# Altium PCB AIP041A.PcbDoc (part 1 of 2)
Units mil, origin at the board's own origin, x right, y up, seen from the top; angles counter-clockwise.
Board outline 2650 x 1600 mil, 2 copper layers (Top Layer, Bottom Layer), stack 62 mil thick; 99 components, 51 nets, 275 pads, 83 vias.
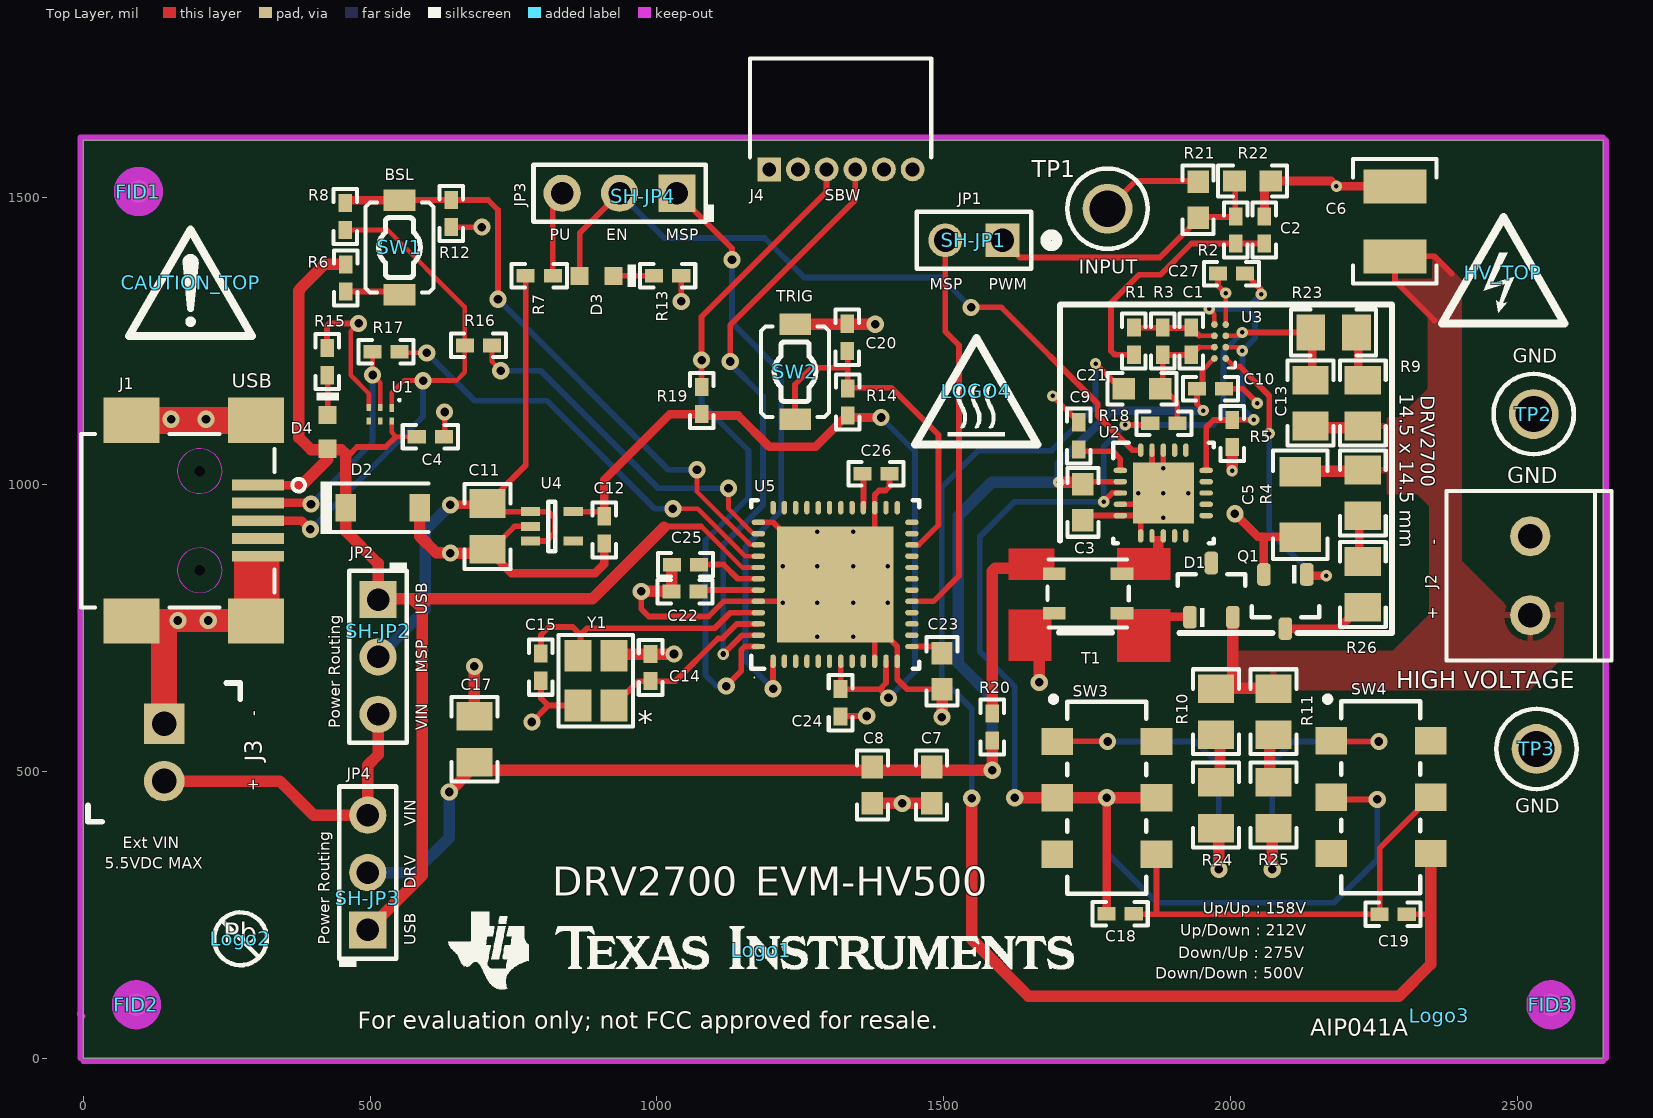
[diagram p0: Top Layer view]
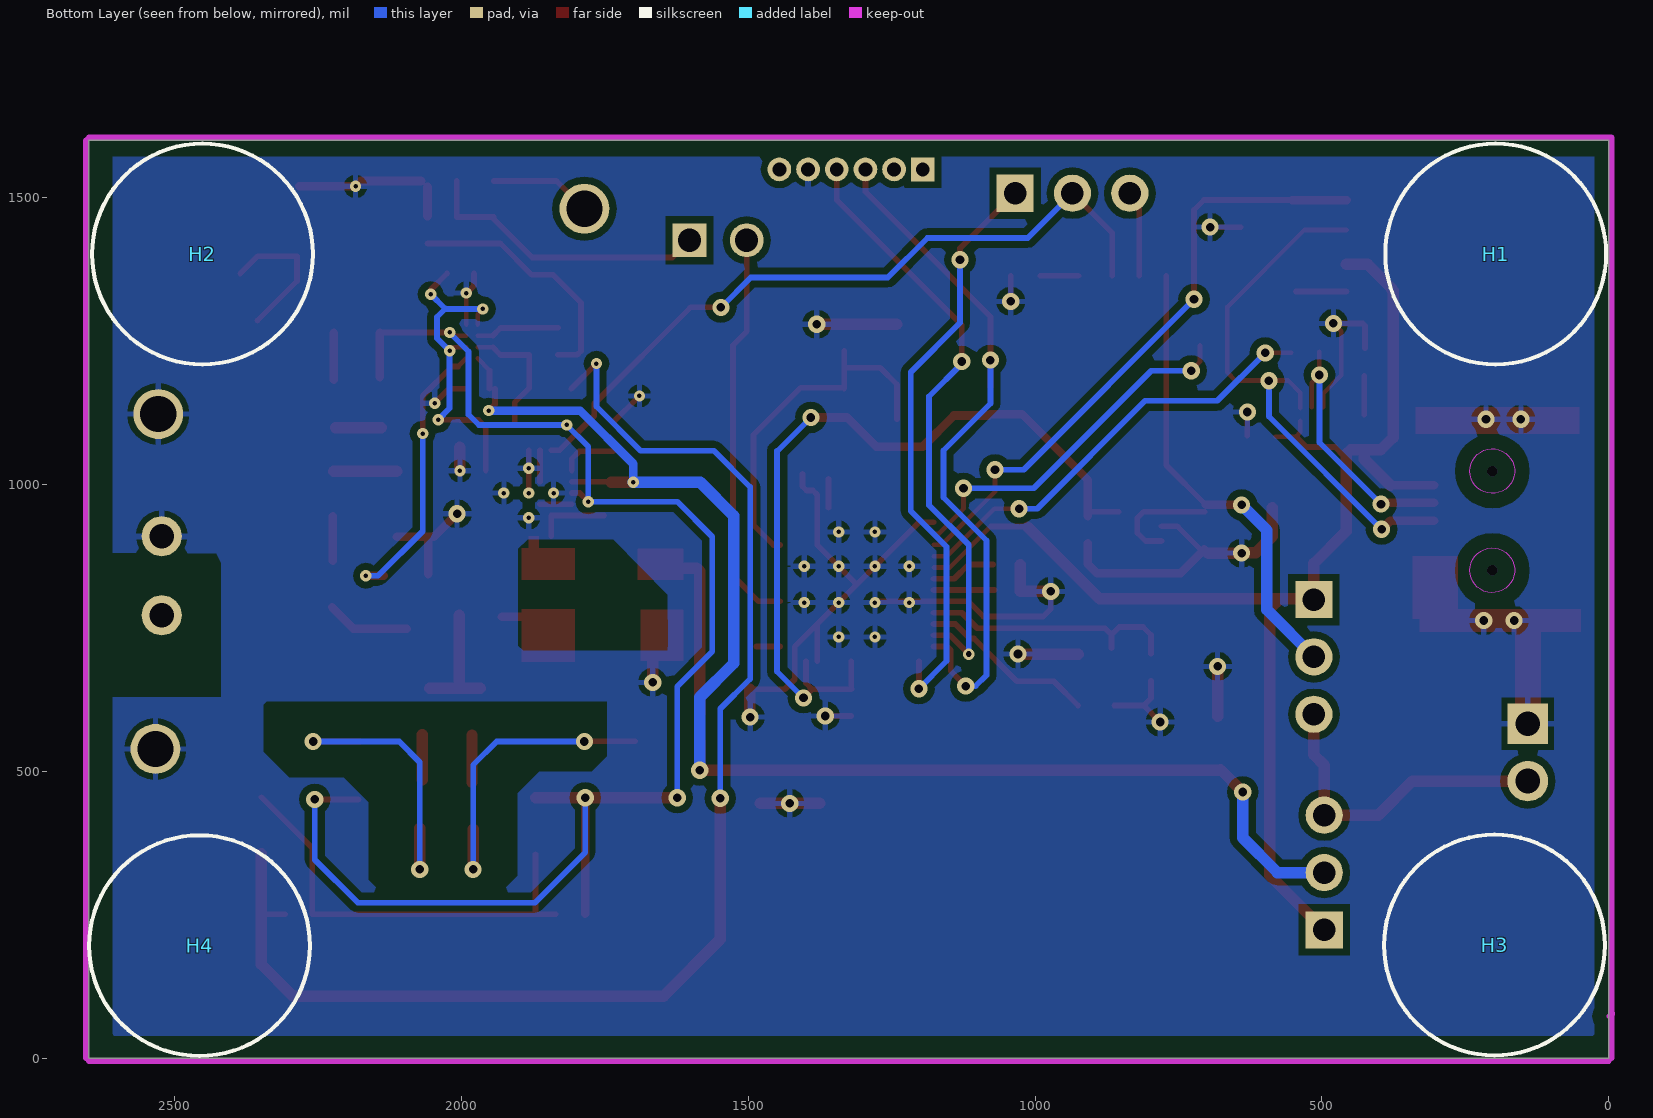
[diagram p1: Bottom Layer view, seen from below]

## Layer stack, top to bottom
Top Layer: signal copper 1.4
Dielectric: core 59.2, FR-4, Dk 4.8
Bottom Layer: signal copper 1.4

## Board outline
0,0 0,1600 2650,1600 2650,0 0,0

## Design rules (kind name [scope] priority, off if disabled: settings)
AcuteAngle [All] p1: minimum=4.50000000000000E+0001 checktracksonly=FALSE
AssemblyTestPointUsage [All] p1: valid=2
Clearance Clearance_BoardEdge_MountingHoles [OnCopper and InComponentClass('Mounting Holes') vs IsKeepOut] p1: gap=30
Clearance Clearance_BoardEdge_Poly [OnCopper and InPoly vs IsKeepOut] p2: gap=25
Clearance Clearance_BoardEdge [OnCopper and Not InComponentClass('Logo') and not InComponentClass('FiducialMark') and not InRegion(1000,500,4000,800) and Not IsKeepout vs IsKeepOut] p3: gap=18
Clearance Clearance_Poly [InPolygon] p4: gap=12
Clearance [All vs InNetClass('HV')] p5: gap=30
ComponentClearance ComponentClearance_Shunt [InComponentClass('Header') vs InComponentClass('Shunt')] p1: gap=0 collisioncheckmode=3 verticalgap=0 showdistances=FALSE
ComponentClearance ComponentClearance_Logo [InComponentClass('Logo')] p2: gap=30 collisioncheckmode=3 verticalgap=10 showdistances=FALSE
ComponentClearance ComponentClearance_ScrewToNut [(HasFootprint('NY PMS 440 0025 PH')) vs (HasFootprint('Keystone_1902C'))] p3: gap=5 collisioncheckmode=3 verticalgap=10 showdistances=FALSE
ComponentClearance ComponentClearance_MountingHoles [InComponentClass('Mounting Holes')] p4: gap=50 collisioncheckmode=3 verticalgap=100 showdistances=FALSE
ComponentClearance ComponentClearance_SmallPassives [HasFootprint('0201*') or HasFootprint('0402*') or HasFootprint('0508') or HasFootprint('0603*') or HasFootprint('0612') or HasFootprint('0805*') or HasFootprint('0815*') or HasFootprint('0830*') or HasFootprint('1206*') or HasFootprint('1210*') or HasFootprint('1808*') or HasFootprint('1812*') or HasFootprint('1825*') or HasFootprint('2010*') or HasFootprint('2220*') or HasFootprint('2225*') or HasFootprint('2512*') or HasFootprint('2728*') or HasFootprint('3518*') vs HasFootprint('0201*') or HasFootprint('0402*') or HasFootprint('0508') or HasFootprint('0603*') or HasFootprint('0612') or HasFootprint('0805*') or HasFootprint('0815*') or HasFootprint('0830*') or HasFootprint('1206*') or HasFootprint('1210*') or HasFootprint('1808*') or HasFootprint('1812*') or HasFootprint('1825*') or HasFootprint('2010*') or HasFootprint('2220*') or HasFootprint('2225*') or HasFootprint('2512*') or HasFootprint('2728*') or HasFootprint('3518*')] p5: gap=12 collisioncheckmode=3 verticalgap=10 showdistances=FALSE
ComponentClearance ComponentClearance_THtoSMT [IsThruComponent vs IsSMTComponent] p6: gap=75 collisioncheckmode=3 verticalgap=30 showdistances=FALSE
ComponentClearance ComponentClearance_THtoTH [IsThruComponent vs IsThruComponent] p7: gap=70 collisioncheckmode=3 verticalgap=30 showdistances=FALSE
ComponentClearance [All] p8: gap=12 collisioncheckmode=3 verticalgap=10 showdistances=FALSE
DiffPairsRouting [All] p1: maxlimit=100 minlimit=10 mostfreqgap=10 maxuncoupledlength=1000
FabricationTestPointUsage TestPointUsage [All] p1: valid=2 allowmultiple=FALSE
FabricationTestpoint Testpoint [All] p1: side=3 testpointundercomponent=TRUE minsize=40 maxsize=100 preferedsize=60 minholesize=0 maxholesize=40 preferedholesize=32 testpointgrid=1 allowsidetop=TRUE allowsidebottom=TRUE usegrid=TRUE gridtolerance=0.01
FanoutControl Fanout_LCC [IsLCC] p1: bgadir=Out bgaviamode=Centered fanoutstyle=Auto fanoutdirection=Alternating viagrid=1 // Fanout_LCC (Default Rule)
FanoutControl Fanout_BGA [IsBGA] p2: bgadir=Out bgaviamode=Centered fanoutstyle=Auto fanoutdirection=Alternating viagrid=1 // Fanout_BGA (Default Rule)
FanoutControl Fanout_Default [All] p4: bgadir=Out bgaviamode=Centered fanoutstyle=Auto fanoutdirection=Alternating viagrid=1 // Fanout_Default (Default Rule)
FanoutControl Fanout_Small [(CompPinCount < 5)] p5: bgadir=Out bgaviamode=Centered fanoutstyle=Auto fanoutdirection=OutThenIn viagrid=1 // Fanout_Small (Default Rule)
HoleSize [All] p1: absolutevalues=TRUE maxlimit=251 minlimit=3 maxpercent=80.000 minpercent=20.000
MinimumAnnularRing MinimumAnnularRing_ThermalPadVias [IsVia and InAnyComponent] p1: minimumring=5.91
MinimumAnnularRing [All] p2: minimumring=2
MinimumSolderMaskSliver MinimumSolderMaskSliver_Logo [InComponentClass('Logo') vs InComponentClass('Logo')] p1: minsoldermaskwidth=0.7
MinimumSolderMaskSliver [All] p2: minsoldermaskwidth=4
PlaneClearance [All] p1: clearance=12
PlaneConnect [All] p1: planeconnectstyle=Relief reliefexpansion=10 reliefentries=4 reliefconductorwidth=10 reliefairgap=10
PolygonConnect [All] p1: connectstyle=Relief reliefconductorwidth=10 reliefentries=4 polygonreliefangle="90 Angle" airgapwidth=10
RoutingVias ThermalPadVias [IsVia and InAnyComponent] p1: holewidth=7.87 width=19.68 viastyle="Through Hole" minholewidth=7.87 minwidth=19.68 maxholewidth=12.99 maxwidth=23.62
RoutingVias [All] p2: holewidth=16 width=34 viastyle="Through Hole" minholewidth=5 minwidth=10 maxholewidth=40 maxwidth=65
SMDToCorner [All] p1 off: distance=30000
SilkToSilkClearance SilkToSilkClearance_Pb-Free [(HasFootprint('Pb-Free_Overlay_Medium') OR HasFootprint('Pb-Free_Overlay_Small')) vs (HasFootprint('Pb-Free_Overlay_Medium') OR HasFootprint('Pb-Free_Overlay_Small'))] p1: silktosilkclearance=0
SilkToSilkClearance [All] p2: silktosilkclearance=2
SilkscreenOverComponentPads [IsPad] p1: minsilkscreentomaskgap=1
SolderMaskExpansion [All] p1: expansion=1
Width [All] p1: maxlimit=100 minlimit=3 preferedwidth=10 checkconnectedcopper=TRUE
13 further rules are at their usual default settings.

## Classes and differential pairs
net class HV: HV NetQ1_3 RNET1 RNET2
component class AssemblyNote: ZZ2 ZZ3 ZZ4
component class FiducialMark: FID1 FID2 FID3
component class AIP041A_Hardware: CAUTION_TOP FID1 FID2 FID3 H1 H2 H3 H4 HV_TOP Logo1 Logo2 Logo3 LOGO4 SH-JP1 SH-JP2 SH-JP3 SH-JP4 ZZ2 ZZ3 ZZ4
component class Logo: Logo1
component class Header: JP1 JP2 JP3 JP4
component class AIP041A: C1 C2 C3 C4 C5 C6 C7 C8 C9 C10 C11 C12 C13 C14 C15 C17 C18 C19 C20 C21 C22 C23 C24 C25 C26 C27 D1 D2 D3 D4 J1 J2 J3 J4 JP1 JP2 JP3 JP4 Q1 R1 R2 R3 R4 R5 R6 R7 R8 R9 R10 R11 R12 R13 R14 R15 R16 R17 R18 R19 R20 R21 R22 R23 R24 R25 R26 SW1 SW2 SW3 SW4 T1 TP1 TP2 TP3 U1 U2 U3 U4 U5 Y1
component class Shunt: SH-JP1 SH-JP2 SH-JP3 SH-JP4

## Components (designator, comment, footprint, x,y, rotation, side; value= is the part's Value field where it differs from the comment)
C1 "GRM1555C1H101JA01D" 0402 1932.12,1250 r90 top
C2 "GRM155R61A102KA01D" 0402 2059.49,1444.01 r90 top
C3 "GRM188R71E104KA01D" 0603 1743,969 r270 top
C4 "GRM155R71C104JA88D" 0402 605,1083.52 r0 top
C5 "GRM31B5C2J102JW01L" 1206 2122,965 r270 top
C6 "GRM32DR72J473KW01L" 1210M 2287,1459 r90 top
C7 "GRM188R71E104KA01D" 0603 1479,476 r270 top
C8 "GRM188R61E106MA73" 0603 1376,476 r270 top
C9 "GRM155R71C104JA88D" 0402 1736,1085 r90 top
C10 "GRM155R71C104JA88D" 0402 1965.38,1167 r0 top
C11 "0805YD106MAT2A" 0805_HV 705,927.15 r270 top
C12 "GRM155R60J102KA01D" 0402 908,921.15 r270 top
C13 "C0805C220KBRACTU" 0805_HV 2140,1142 r90 top
C14 "GRM1555C1H100JA01D" 0402 989,680.9 r270 top
C15 "GRM1555C1H100JA01D" 0402 798,681.52 r90 top
C17 "0805YD106MAT2A" 0805_HV 682,556 r90 top
C18 "GRM155R71E562KA01D" 0402 1808,252 r0 top
C19 "GRM155R71H332KA01D" 0402 2284,251 r0 top
C20 "C1005X5R0J104K" 0402 1332.05,1256.84 r90 top
C21 "GRM188R72A472KA01D" 0603 1846,1167 r0 top
C22 "GRM155C80J224KE01D" 0402 1049.38,813.52 r180 top
C23 "C0603C474K8RACTU" 0603 1497.29,674.57 r270 top
C24 "C1005X5R0J104K" 0402 1320.29,619.57 r90 top
C25 "GRM155C80J224KE01D" 0402 1050,860.52 r180 top
C26 "C1005X5R0J104K" 0402 1382,1018.52 r180 top
C27 "GRM155R71C104JA88D" 0402 2002,1368 r180 top
CAUTION_TOP "CAUTION.  READ USER GUIDE BEFORE USE" IEC_Caution_Small 187,1352 r0 top
D1 "MMBD3004S-7-F" SOT-23 1967,816 r90 top
D2 "MMSZ5232B-7-F" SOD-123 522,959.52 r0 top
D3 "LTST-C190KGKT" LED_LTST-C190_G 895,1364 r0 top
D4 "LTST-C190KGKT" LED_LTST-C190_G 426,1092.03 r90 top
FID1 "Fiducial" Fiducial10-20 96,1511 r0 top
FID2 "Fiducial" Fiducial10-20 92.5,93 r0 top
FID3 "Fiducial" Fiducial10-20 2559,93 r0 top
H1 "SJ61A2" Bumpon_SJ61A2 197,1402 r270 bottom
H2 "SJ61A2" Bumpon_SJ61A2 2452,1402 r270 bottom
H3 "SJ61A2" Bumpon_SJ61A2 199,197 r270 bottom
H4 "SJ61A2" Bumpon_SJ61A2 2457,196 r270 bottom
HV_TOP "DANGER HIGH VOLTAGE" IEC_HighVoltage_Small 2476,1369 r0 top
J1 "USB" MILLMAX_897-43-005-00-100001 152,937 r270 top
J2 "1751248" CONN_1751248 2523,841 r90 top
J3 "1725656" CONN_1725656 141,533 r270 top
J4 "LPPB061NGCN-RC" SULLINS_LPPB061NGCN-RC 1321,1649.52 r180 top
JP1 "5-146261-1" CONN_5-146261-1 1553,1426 r180 top
JP2 "5-146278-3" TE_5-146278-3 514,699.52 r270 top
JP3 "5-146278-3" TE_5-146278-3 935,1508 r180 top
JP4 "5-146278-3" TE_5-146278-3 496,323.52 r90 top
Logo1 "Texas Instruments" TI_Horizontal_Overlay_Small 1182,188 r0 top
Logo2 "Pb-Free Symbol" Pb-Free_Overlay_Small 274,208 r0 top
Logo3 "FCC disclaimer" FCC_disclaimer 2364,74 r0 top
LOGO4 "CAUTION HOT SURFACE" IEC_HotSurface_Small 1557,1163 r0 top
Q1 "BSS127 H6327" SOT-23 2096,796 r270 top
R1 "CRCW0402100KFKED" 0402 1832,1250 r90 top
R2 "CRCW04024K99FKED" 0402 2009.49,1444.01 r270 top
R3 "CRCW040275K0JNED" 0402 1882.12,1250 r90 top
R4 "CRCW08052K40JNEA" 0805_HV 2231,985.49 r90 top
R5 "CRCW040210K0JNED" 0402 2003,1089 r270 top
R6 "CRCW0402100RFKED" 0402 457.37,1360.38 r90 top
R7 "CRCW04023K30JNED" 0402 795,1364 r180 top
R8 "CRCW04021K40FKED" 0402 457,1467.52 r270 top
R9 "CRCW08051M00FKEA" 0805_HV 2231,1142 r270 top
R10 "RT0805BRD07750KL" 0805_HV 1975,604 r90 top
R11 "CRCW08051M24FKEA" 0805_HV 2075,604 r90 top
R12 "CRCW04021M00JNED" 0402 641.52,1472.51 r90 top
R13 "CRCW0402511RFKED" 0402 1019,1364 r180 top
R14 "CRCW040210K0JNED" 0402 1333.05,1143.84 r270 top
R15 "CRCW0402511RFKED" 0402 425,1214.24 r270 top
R16 "CRCW040233R0JNED" 0402 689,1242.52 r180 top
R17 "CRCW040233R0JNED" 0402 528,1231.52 r180 top
R18 "CRCW04025K49FKED" 0402 1884,1107 r180 top
R19 "CRCW04029K76FKED" 0402 1078,1146.52 r270 top
R20 "RC0402JR-070RL" 0402 1585,577 r270 top
R21 "CRCW06030000Z0EA" 0603 1943.8,1496.51 r90 top
R22 "CRCW06030000Z0EA" 0603 2038.8,1529.29 r180 top
R23 "CRCW08051M05FKEA" 0805_HV 2180,1265 r0 top
R24 "RT0805BRD07750KL" 0805_HV 1975,441 r90 top
R25 "CRCW08051M24FKEA" 0805_HV 2075,441 r90 top
R26 "CRCW08052K40JNEA" 0805_HV 2231,826 r90 top
SH-JP1 "2SN-BK-G" 2SN-BK-G 1553,1426 r180 top
SH-JP2 "2SN-BK-G" 2SN-BK-G 514,744.39 r90 top
SH-JP3 "2SN-BK-G" 2SN-BK-G 496,278.66 r90 top
SH-JP4 "2SN-BK-G" 2SN-BK-G 976.68,1503.01 r180 top
SW1 "BSL" SW_TL1015AF160QG 551.37,1413.38 r270 top
SW2 "TRIG" SW_TL1015AF160QG 1241.05,1196.84 r270 top
SW3 "CL-SB-22B-02T" SW_CL-SB-22B-02 1784.59,453.88 r0 top
SW4 "CL-SB-22B-02T" SW_CL-SB-22B-02 2262.59,454.88 r0 top
T1 "ATB322515-0110" XFMR_ATB3215 1752,810 r270 top
TP1 "INPUT" Keystone5013 1786,1481 r0 top
TP2 "GND" Keystone5011 2529,1123 r90 top
TP3 "GND" Keystone5011 2534,539 r0 top
U1 "TPD4E004DRY" DRY0006A 517.8,1122.73 r270 top
U2 "DRV2700RGP" RGP0020D 1883.08,985.27 r0 top
U3 "OPA2376AIYZD" YZD0008ANAP 1982.12,1249.5 r180 top
U4 "TLV70033DCKR" DCK0005A_N 817,927.15 r0 top
U5 "MSP430F5510IRGZ" RGZ0048A 1310.99,825.88 r90 top
Y1 "ABM8G-12.000MHZ-B4Y-T" XTAL_NX3225SA 893.82,658.01 r90 top
ZZ2 "These assemblies are ESD sensitive, ESD precautions shall be observed." AssemblyNote 185,3829.11 r0 top
ZZ3 "These assemblies must be clean and free from flux and all contaminants. Use of no clean flux is not acceptable." AssemblyNote 185,3740.56 r0 top
ZZ4 "These assemblies must comply with workmanship standards IPC-A-610 Class 2, unless otherwise specified." AssemblyNote 185,3652 r0 top

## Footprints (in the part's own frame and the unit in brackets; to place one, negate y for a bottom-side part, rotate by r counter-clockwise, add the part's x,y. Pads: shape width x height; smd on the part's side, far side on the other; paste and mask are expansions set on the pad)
2SN-BK-G [mil] "Samtec STEP model"
  round 1 on Mech3: 0(0,0)
  body extent -78,-39 79,39, height 188
0402 [mm] "0402 from SM-752 data"
  rect 0.8x0.6 smd: 1(-0.6,0) 2(0.6,0)
  silkscreen extent -1.22,-0.52 1.22,0.52, body extent -0.55,-0.3 0.55,0.3, height 0.6
0603 [mm] "0603 from SM-752 data"
  rect 1x0.95 smd: 1(-0.8,0) 2(0.8,0)
  silkscreen extent -1.52,-0.69 1.52,0.69, body extent -0.87,-0.47 0.87,0.47, height 0.85
0805_HV [mil] "0805 with 30mil clearance between pads"
  rect 50x63 smd: 1(-40,0) 2(40,0)
  silkscreen extent -74,-40 74,40, body extent -43,-29 43,29, height 43
1206 [mm] "1206 from SM-752 data"
  rect 1.3x1.85 smd: 1(-1.45,0) 2(1.45,0)
  silkscreen extent -2.4,-1.21 2.4,1.21, body extent -1.7,-0.9 1.7,0.9, height 1.35
1210M [mm] "1210 from SM-752 data"
  rect 1.5x2.8 smd: 1(-1.55,0) 2(1.55,0)
  silkscreen extent -2.75,-1.85 2.75,1.85, body extent -1.7,-1.35 1.7,1.35, height 1.35
AssemblyNote [mil] "Assembly Note"
Bumpon_SJ61A2 [mil] "3M Hemispherical Bumpon transparent"
  round 1 on Mech4: 0(0,0)
  silkscreen extent -192,-192 192,192, body extent -191,-192 193,192, height 250
CONN_5-146261-1 [mm] "Sullins"
  rect 1.5x1.5 hole 1.02: 1(-1.27,0)
  round 1.5 hole 1.02: 2(1.27,0)
  silkscreen extent -3.68,-1.27 2.54,1.27, body extent -2.51,-1.27 2.51,1.27, height 10.87
CONN_1725656 [mm] "Phoenix Contact"
  rect 1.8x1.8 hole 1.1: 1(-1.27,0)
  round 1.8 hole 1.1: 2(1.27,0)
  silkscreen extent -3.08,-3.37 3.08,3.37, body extent -2.77,-3.1 2.77,3.1, height 8.52
CONN_1751248 [mil] "Phoenix Contact"
  round 70 hole 43.31: 1(-68.9,0) 2(68.9,0)
  silkscreen extent -148,-142 148,146, body extent -148,-142 148,146, height 335
DCK0005A_N [mm] "SOT353, 5-Leads, Body 2x1.3mm, Pitch 0.65mm, Lead Span 2.1mm, IPC Medium Density"
  rect 0.85x0.4 smd: 1(-0.95,0.65) 2(-0.95,0) 3(-0.95,-0.65) 4(0.95,-0.65) 5(0.95,0.65)
  silkscreen extent -0.15,-1.1 0.15,1.1, body extent -1.14,-1 1.14,1, height 0.94
DRY0006A [mm] "PSON, 6-Leads, Body 1x1.45mm, Pitch 0.5mm, TI Recommended"
  rect 0.35x0.2 smd: 1(-0.275,0.5)
  rect 0.3x0.2 smd: 2(-0.3,0) 3(-0.3,-0.5) 4(0.3,-0.5) 5(0.3,0) 6(0.3,0.5)
  silkscreen extent -0.67,0.8 -0.58,0.9, body extent -0.53,-0.75 0.53,0.75, height 0.61
FCC_disclaimer [mil]
Fiducial10-20 [mm]
  round 1 smd mask+0.5: 1(0,0)
  Top Layer keep-out circle w1.178: c0,0 r0.5
IEC_Caution_Small [mil]
  silkscreen extent -107,-93 107,92
IEC_HighVoltage_Small [mil]
  silkscreen extent -107,-88 107,97
IEC_HotSurface_Small [mil]
  silkscreen extent -107,-93 107,92
Keystone5011 [mil] "Keystone Multipurpose loops"
  round 87 hole 63: 1(0,0)
  silkscreen extent -70,-70 70,70, body extent -63,-63 63,62, height 319
Keystone5013 [mil] "Keystone Multipurpose loops"
  round 87 hole 63: 1(0,0)
  silkscreen extent -70,-70 70,70, body extent -63,-63 63,62, height 319
LED_LTST-C190_G [mm] "Lite-On"
  rect 0.8x0.8 smd: 1(-0.75,0) 2(0.75,0)
  silkscreen extent 1.37,-0.5 1.75,0.5, body extent -0.85,-0.45 0.85,0.45, height 0.9
MILLMAX_897-43-005-00-100001 [mil] "Mill-Max"
  rect 19x91 smd: 1(-62,152.5) 2(-31,152.5) 3(0,152.5) 4(31,152.5) 5(62,152.5)
  rect 79x98 smd: 6(175,149) 7(-175,149) 8(-175,-68) 9(175,-68)
  round 5 hole 18 unplated: MH1(-86.5,51) MH2(86.5,51)
  Multi-Layer keep-out circle w1: c-86.5,51 r39
  Multi-Layer keep-out circle w1: c86.5,51 r39
  silkscreen extent -152,-156 152,234, body extent -151,-181 151,181, height 156
Pb-Free_Overlay_Small [mil]
  silkscreen extent -46,-46 46,46
RGP0020D [mm] "QFN, 20-Leads, Body 4x4mm, Pitch 0.5mm, Thermal Pad 2.7x2.7mm, TI Recommended"
  oval 0.6x0.24 smd: 1(-1.9,1) 2(-1.9,0.5) 3(-1.9,0) 4(-1.9,-0.5) 5(-1.9,-1) 11(1.9,-1) 12(1.9,-0.5) 13(1.9,0) 14(1.9,0.5) 15(1.9,1)
  oval 0.24x0.6 smd: 6(-1,-1.9) 7(-0.5,-1.9) 8(0,-1.9) 9(0.5,-1.9) 10(1,-1.9) 16(1,1.9) 17(0.5,1.9) 18(0,1.9) 19(-0.5,1.9) 20(-1,1.9)
  rect 2.7x2.7 smd paste-1.35: 21(0,0)
  silkscreen extent -2.22,-2.22 2.22,2.22, body extent -2.07,-2.07 2.07,2.07, height 1.01
RGZ0048A [mm] "QFN, 48-Leads, Body 7x7mm, Pitch 0.5mm, Thermal Pad 5.15X5.15mm, TI recommended"
  oval 0.6x0.24 smd: 1(-3.4,2.75) 2(-3.4,2.25) 3(-3.4,1.75) 4(-3.4,1.25) 5(-3.4,0.75) 6(-3.4,0.25) 7(-3.4,-0.25) 8(-3.4,-0.75) 9(-3.4,-1.25) 10(-3.4,-1.75) 11(-3.4,-2.25) 12(-3.4,-2.75) 25(3.4,-2.75) 26(3.4,-2.25) 27(3.4,-1.75) 28(3.4,-1.25) 29(3.4,-0.75) 30(3.4,-0.25) 31(3.4,0.25) 32(3.4,0.75) 33(3.4,1.25) 34(3.4,1.75) 35(3.4,2.25) 36(3.4,2.75)
  oval 0.24x0.6 smd: 13(-2.75,-3.4) 14(-2.25,-3.4) 15(-1.75,-3.4) 16(-1.25,-3.4) 17(-0.75,-3.4) 18(-0.25,-3.4) 19(0.25,-3.4) 20(0.75,-3.4) 21(1.25,-3.4) 22(1.75,-3.4) 23(2.25,-3.4) 24(2.75,-3.4) 37(2.75,3.4) 38(2.25,3.4) 39(1.75,3.4) 40(1.25,3.4) 41(0.75,3.4) 42(0.25,3.4) 43(-0.25,3.4) 44(-0.75,3.4) 45(-1.25,3.4) 46(-1.75,3.4) 47(-2.25,3.4) 48(-2.75,3.4)
  rect 5.15x5.15 smd paste-2.6: 49(0,0)
  silkscreen extent -3.72,-3.72 3.72,3.72, body extent -3.58,-3.57 3.57,3.58, height 1.01
SOD-123 [mm] "On Semi recommended land pattern"
  rect 0.915x1.22 smd: 1(-1.637,0) 2(1.637,0)
  silkscreen extent -2.74,-1.17 2.03,1.17, body extent -1.93,-0.9 1.93,0.9, height 1.35
SOT-23 [mm] "SOT23, 3-Leads, Body 2.9x1.3mm, Pitch 0.95mm, Lead Span 2.5mm, IPC Medium Density"
  rrect50% 1x0.6 smd: 1(-1.2,0.95) 2(-1.2,-0.95) 3(1.2,0)
  silkscreen extent -1.63,-1.5 0.7,1.5, body extent -1.16,-1.45 1.21,1.45, height 1
SULLINS_LPPB061NGCN-RC [mm] "SULLINS"
  rect 1.05x1.05 hole 0.61: 1(3.175,2.54)
  round 1.05 hole 0.61: 2(1.905,2.54) 3(0.635,2.54) 4(-0.635,2.54) 5(-1.905,2.54) 6(-3.175,2.54)
  silkscreen extent -4,-2.37 4.03,2, body extent -4,-2.36 4,2.59, height 2.16
SW_CL-SB-22B-02 [mm] "SMD, 6-Leads, Body 8.5x3.5mm, Pitch 2.5mm"
  rect 1.4x1.2 smd: 1(-2.2,2.5) 2(-2.2,0) 3(-2.2,-2.5) 4(2.2,2.5) 5(2.2,0) 6(2.2,-2.5)
  silkscreen extent -2.48,-4.25 1.75,4.49, body extent -1.75,-4.25 1.75,4.25, height 5.5
SW_TL1015AF160QG [mm] "E-Switch"
  rect 0.95x1.4 smd: 1(-2.1,0) 2(2.1,0)
  silkscreen extent -2,-1.5 2,1.5, body extent -2.3,-1.5 2.3,1.5, height 2
TE_5-146278-3 [mm] "TE CONNECTIVITY"
  rect 1.65x1.65 hole 1: 1(-2.54,0)
  round 1.65 hole 1: 2(0,0) 3(2.54,0)
  silkscreen extent -4.19,-1.27 3.81,1.27, body extent -3.68,-1.17 3.68,1.17, height 8.13
TI_Horizontal_Overlay_Small [mil]
  silkscreen extent -545,-68 545,67
XFMR_ATB3215 [mm] "TDK"
  rect 0.55x1 smd: 1(-0.875,1.5) 2(0.875,1.5) 3(0.875,-1.5) 4(-0.875,-1.5)
  silkscreen extent -1.5,-1.8 1.5,1.8, body extent -1.4,-1.75 1.4,1.75, height 1.55
XTAL_NX3225SA [mm] "NDK NX3225SA recommended land pattern"
  rect 1.4x1.2 smd: 1(-1.1,-0.8) 2(1.1,-0.8) 3(1.1,0.8) 4(-1.1,0.8)
  silkscreen extent -2.03,-1.65 2.03,1.65, body extent -1.65,-1.3 1.65,1.3, height 0.7
YZD0008ANAP [mm] "WCSP"
  round 0.3 smd paste-0.1 mask+0.04: A1(-0.25,0.75) A2(0.25,0.75) B1(-0.25,0.25) B2(0.25,0.25) C1(-0.25,-0.25) C2(0.25,-0.25) D1(-0.25,-0.75) D2(0.25,-0.75)
  silkscreen extent -0.67,0.92 -0.35,1.17, body extent -0.57,-1.09 0.57,1.09, height 0.63

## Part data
C1: "CAP, CERM, 100 pF, 50 V, +/- 5%, C0G/NP0, 0402"
C2: "CAP, CERM, 1000 pF, 10 V, +/- 10%, X5R, 0402"
C3 C7: "CAP, CERM, 0.1 µF, 25 V, +/- 10%, X7R, 0603"
C4 C9 C10 C27: library part 0402YC132KAT2A, "CAP CER 0.1UF 16V 5% X7R 0402"
C5: "CAP, CERM, 1000 pF, 630 V, +/- 5%, C0G/NP0, 1206"
C6: "CAP, CERM, 0.047 µF, 630 V, +/- 10%, X7R, 1210"
C8: "CAP, CERM, 10 µF, 25 V, +/- 20%, X5R, 0603"
C11 C17: "CAP, CERM, 10uF, 16V, +/-20%, X5R, 0805"
C12: "CAP, CERM, 1000pF, 6.3V, +/-10%, X5R, 0402"
C13: "CAP, CERM, 22 pF, 630 V, +/- 10%, X7R, 0805_140"
C14 C15: "CAP, CERM, 10pF, 50V, +/-5%, C0G/NP0, 0402"
C18: "CAP, CERM, 5600 pF, 25 V, +/- 10%, X7R, 0402"
C19: "CAP, CERM, 3300 pF, 50 V, +/- 10%, X7R, 0402"
C20 C24 C26: "CAP, CERM, 0.1uF, 6.3V, +/-10%, X5R, 0402"
C21: "CAP, CERM, 4700 pF, 100 V, +/- 10%, X7R, 0603"
C22 C25: "CAP, CERM, 0.22uF, 6.3V, +/-10%, X6S, 0402"
C23: "CAP, CERM, 0.47uF, 10V, +/-10%, X7R, 0603"
CAUTION_TOP: library part IEC_Caution, "IEC 61010-1 Caution Warning"
D1: "Diode, Switching, 350 V, 0.225 A, SOT-23"
D2: "Diode, Zener, 5.6V, 500 mW, SOD-123"
D3 D4: "LED, Green, SMD"
FID1 FID2 FID3: "Fiducial mark.  There is nothing to buy or mount."
H1 H2 H3 H4: "Bumpon, Hemisphere, 0.375 X 0.235, Black"
HV_TOP: library part IEC_HighVoltage, "IEC 61010-1 High Voltage Warning"
J1: library part 897-43-005-00-100001, "Connector, USB Mini B"
J2: "Conn Term Block, 2POS, 3.5mm, TH"
J3: "Header, 2 Pos, 6A, 63V, TH"
J4: "Receptacle, 50mil, 6x1, R/A, TH"
JP1: "Header, 100mil, 2x1, Gold, TH"
JP2 JP3 JP4: "Header, 100mil, 3x1, Tin, TH"
Logo1: library part TI_Logo, "Texas Instrument Corporate Signature"
Logo2: library part Pb-Free
Logo3: library part FCC_disclaimer, "FCC_disclaimer"
LOGO4: library part IEC_HotSurface, "IEC 61010-1 Hot Surface Warning"
Q1: "MOSFET, N-CH, 600 V, 0.021 A, SOT-23"
R1: "RES, 100 k, 1%, 0.063 W, 0402"
R2: "RES, 4.99 k, 1%, 0.063 W, 0402"
R3: "RES, 75 k, 5%, 0.063 W, 0402"
R4 R26: "RES, 2.4 k, 5%, 0.125 W, 0805"
R5: "RES, 10 k, 5%, 0.063 W, 0402"
R6: "RES, 100 ohm, 1%, 0.063W, 0402"
R7: "RES, 3.3k ohm, 5%, 0.063W, 0402"
R8: "RES, 1.40k ohm, 1%, 0.063W, 0402"
R9: "RES, 1.00 M, 1%, 0.125 W, 0805"
R10 R24: "RES, 750 k, 0.1%, 0.125 W, 0805"
R11 R25: "RES, 1.24 M, 1%, 0.125 W, 0805"
R12: "RES, 1.0Meg ohm, 5%, 0.063W, 0402"
R13 R15: "RES, 511 ohm, 1%, 0.063W, 0402"
R14: "RES, 10k ohm, 5%, 0.063W, 0402"
R16 R17: "RES, 33 ohm, 5%, 0.063W, 0402"
R18: "RES, 5.49 k, 1%, 0.063 W, 0402"
R19: "RES, 9.76k ohm, 1%, 0.063W, 0402"
R20: "RES, 0, 5%, 0.063 W, 0402"
R21 R22: "RES, 0, 5%, 0.1 W, 0603"
R23: "RES, 1.05 M, 1%, 0.125 W, 0805"
SH-JP1 SH-JP2 SH-JP3 SH-JP4: "Shunt, 2mm, Gold plated, Black"
SW1 SW2: library part TL1015AF160QG, "Switch, Tactile, SPST-NO, 0.05A, 12V, SMT"
SW3 SW4: "Switch, Slide, DPDT, 0.2A, GULL, 12V, SMD"
T1: "Transformer, Xenon Flash, 7uH, SMT"
TP1: library part 5013, "Test Point, Multipurpose, Orange, TH"
TP2 TP3: library part 5011, "Test Point, Multipurpose, Black, TH"
U1: "4-CHANNEL ESD-PROTECTION ARRAY FOR HIGH-SPEED DATA INTERFACES, DRY006A"
U2: "Piezo Driver with Integrated Boost Converter, RGP0020D"
U3: "Low-Noise, Low Quiescent Current, Precision Operational Amplifier e-trim Series"
U4: "Single Output LDO, 200 mA, Fixed 3.3 V Output, 2 to 5.5 V Input, with Low IQ, 5-pin SC70 (DCK), -40 to 125 degC, Green (RoHS & no Sb/Br)"
U5: "Mixed Signal MicroController, RGZ0048A"
Y1: "CRYSTAL 12.000MHZ 10PF SMD"
ZZ2 ZZ3 ZZ4: library part AssemblyNote

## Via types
v1: diameter 30, hole 15, Top Layer to Bottom Layer, tented both sides, 48 vias
v2: diameter 19.68, hole 7.87, Top Layer to Bottom Layer, tented both sides, 17 vias
v3: diameter 19.68, hole 7.87, Top Layer to Bottom Layer, tented bottom, 17 vias
v4: diameter 20, hole 10, Top Layer to Bottom Layer, tented both sides, 1 vias

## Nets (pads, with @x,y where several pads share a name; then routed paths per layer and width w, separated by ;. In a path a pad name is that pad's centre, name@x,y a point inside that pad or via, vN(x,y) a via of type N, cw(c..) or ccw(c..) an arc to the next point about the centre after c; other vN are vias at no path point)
3P3: C12.1 C24.2 R14.2 R19.2 U4.5 U5.7 U5.11 | length 1403.9
  Top Layer w10: U4.5@854.4,952.74 C12.1@900.03,952.74 ; C24.2@1320.29,643.2 1388.91,643.2 ; C24.2@1320.83,643.74 U5.7@1320.83,692.02 ; U5.11@1399.57,692.02 1399.57,653.85 1388.91,643.2 ; v1(1404,628.11) 1388.91,643.2
  Top Layer w15: C12.1@908,944.77 908,1008 1022.9,1122.9 R19.2@1078,1122.9 ; R19.2@1081.38,1120.52 1141.48,1120.52 1196,1066 1276.84,1066 1327.84,1117 v1(1391,1117)
  Bottom Layer w10: v1(1391,1117) 1449.5,1058.5 ; v1(1404,628.11) 1450,674.11 1450,1059
CNET1: C18.2 C19.1 SW3.6 SW4.5 | length 766.8
  Top Layer w10: C18.2@1836,251 C19.1@2260.38,251 2260.38,366.06 SW4.5@2349.2,454.88 ; 1871.2,253.67 SW3.6@1871.2,355.46
CNET2: C19.2 C21.1 SW4.6 | length 2368.5
  Top Layer w10: v2(1765,1211) C21.1@1809,1167 ; C19.2@2307.62,251 2345,251
  Top Layer w20: v1(1549,453) 1549,207 1648,108 2294,108 2349.2,163.2 SW4.6@2349.2,356.46
  Bottom Layer w10: v1(1549,453) 1549,609 1497,661 1497,996 1560,1059 1688,1059 1765,1136 v2(1765,1211)
D+: J1.3 R8.2 R16.2 U1.1 | length 984.4
  Top Layer w8: R8.2@457,1443.9 530.62,1443.9 664.38,1310.15 ; U1.1@537.48,1133.56 537.48,1160.01 559,1181.52 651,1181.52 665.38,1195.9 665.38,1310.15
  Top Layer w15: J1.3@304.5,937 381,937 v1(396,922)
  Bottom Layer w10: v1(396,922) 592.5,1118.5 v1(592.5,1181.02)
D-: J1.2 R17.2 U1.2 | length 462.7
  Top Layer w8: R17.2@504.38,1231.52 v1(504.38,1191.15) 517.8,1177.72 U1.2@517.8,1134.54
  Top Layer w15: J1.2@304.5,968 v1@395,968
  Bottom Layer w10: v1(397,966) 504.38,1073.38 v1(504.38,1191.15)
EN: D3.1 JP3.2 U2.20 | length 1279.4
  Top Layer w10: D3.1@865.47,1364 865.47,1438.47 JP3.2@935,1508 ; v1(1548,1309) 1601,1309 1769,1141 1769,1120 1828.93,1060.07 U2.20@1843.71,1060.07
  Bottom Layer w10: JP3.2@935,1508 1012.98,1430.02 1187.98,1430.02 1257,1361 1496,1361 v1(1548,1309)
EN_MSP: JP3.1 U5.1 | length 1060.3
  Top Layer w10: JP3.1@1035,1508 1131,1412 v1(1131,1392) ; v1(1202.72,644) U5.1@1202.72,692.02
  Bottom Layer w10: JP3.1@1035,1508 JP3.1@1062,1508 ; v1(1131,1392) 1131,1282 1217,1196 1217,954 1154.43,891.43 1154.43,692.29 v1(1202.72,644)
FILTER_OUT: C1.1 C21.2 R3.1 R18.1 U3.B2 | length 225.8
  Top Layer w8: 1945.9,1239.66 U3.B2@1972.28,1239.66
  Top Layer w10: R3.1@1882.12,1226.38 R3.1@1882.12,1225.88 ; R18.1@1907.62,1107 1907.62,1143.13 1882.12,1168.63 R3.1@1882.12,1225.88 ; 1945.9,1239.66 1932.12,1225.88 R3.1@1882.12,1225.88
GND: C2.2 C3.2 C4.2 C5.2 C6.2 C7.2 C8.2 C9.2 C10.2 C11.2 C12.2 C14.1 C15.1 C17.2 C20.2 C22.2 C23.2 C24.1 C25.2 C26.1 C27.2 D2.2 J1.5 J1.6 J1.7 J1.8 J1.9 J2.2 J3.1 J4.5 Q1.2 R5.2 R12.1 R13.1 R15.1 R22.1 SW2.1 T1.3 TP2.1 TP3.1 U1.3 U2.4 U2.5 U2.6 U2.18 U2.19 U2.21 U3.D1 U4.2 U5.10 U5.12 U5.27 U5.37 U5.44 U5.49 Y1.2 Y1.4 | length 3923.1
  Top Layer w8: v1(480,1281) 466,1267 466,1190.52 498.11,1158.41 U1.3@498.11,1134.54 ; U3.D1@1991.96,1279.03 v2@1991.96,1337
  Top Layer w10: R15.1@425,1237.86 425,1277.03 428.97,1281 v1(480,1281) ; C4.2@630,1084.9 v1(630,1126.52) ; R12.1@641.52,1448.89 v1(695,1448.89) ; C11.2@709.85,884.99 752,927.15 U4.2@779.6,927.15 ; v1(782.12,586) 810.82,614.7 ; C15.1@798,657.9 798,627.52 810.82,614.7 ; Y1.4@862.32,614.7 810.82,614.7 ; v1(972.8,813.72) 972.8,783.2 986,770 1090,770 1116.35,796.35 U5.44@1177.13,796.35 U5.49@1279.35,796.35 ; v1(1042.62,1319.38) R13.1@1042.62,1364 ; U5.37@1177.13,934.15 1202.72,934.15 U5.49@1310.99,825.88 ; C24.1@1320.86,596.52 v1(1366,596.52) ; U5.10@1379.88,692.02 U5.49@1379.88,756.98 ; C26.1@1405.62,1018.52 1405.62,996.65 1398.78,989.81 1387.52,989.81 1379.88,982.17 U5.27@1379.88,959.74 1379.88,894.78 U5.49@1310.99,825.88 ; C23.2@1497.29,643.08 1436.79,643.08 1419.25,660.61 U5.12@1419.25,692.02 1419.25,717.61 U5.49@1379.88,756.98 ; v2(1690,1154.62) C9.2@1736,1108.62 ; C3.2@1751.4,945.9 U2.5@1808.28,945.9 1843.71,945.9 U2.6@1843.71,910.47 ; U2.4@1808.28,965.58 U2.21@1863.4,965.58 ; U2.21@1863.4,1004.95 U2.19@1863.4,1060.07 ; v3(1883.08,985.27) v3(1883.08,1028.58) U2.18@1883.08,1060.07 ; C27.2@1978.38,1368 1978.38,1346.59 v2@1991.96,1333 ; C10.2@1989,1167 2022,1167 v2(2047,1142) ; U5.49@1310.99,825.88 U5.49@1379.88,756.98
  Top Layer w15: C11.2@705,887.15 746.62,845.52 892.38,845.52 908,861.15 C12.2@908,897.52 ; v1(2008,949) 2048.09,908.91 2058,908.91 ; Q1.2@2058,843.84 2058,908.91 ; C2.2@2059.49,1467.64 R22.1@2059.49,1519 ; R22.1@2070.3,1529.29 2175.71,1529.29 v2(2185,1520) C6.2@2283.09,1520 ; C5.2@2113,908.91 2058,908.91
  Top Layer w20: D2.2@586.47,959.52 586.47,910.05 615,881.52 v1@640,881.52 ; v1(640,880.52) C11.2@698.38,880.52 ; C17.2@682,596 v1(682,683) ; Y1.2@925.31,704.52 v1(1030,704.52) ; v1(972.8,813.72) 1025.96,813.72 1026.38,814.15 C25.2@1026.38,860.52 ; SW2.1@1241.05,1279.52 v1(1381,1279.52) ; C8.2@1376,444.5 C7.2@1479,444.5 ; v1@1497.29,595.95 C23.2@1497.29,643.08 ; v1(1667,655) 1667,714 ; v2(2003,1024) R5.2@2003,1065.38
  other v1: 1428,444 1497,594.52 165,763 218,763 153,1114 214,1114
  other v2: 1992,1334
  other v3: 1279.35,734.34 1342.62,734.34 1219.45,794.24 1279.35,794.24 1342.62,794.24 1402.52,794.24 1219.45,857.51 1279.35,857.51 1342.62,857.51 1402.52,857.51 1279.35,917.41 1342.62,917.41 1883.08,941.96 1839.78,985.27 1926.39,985.27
